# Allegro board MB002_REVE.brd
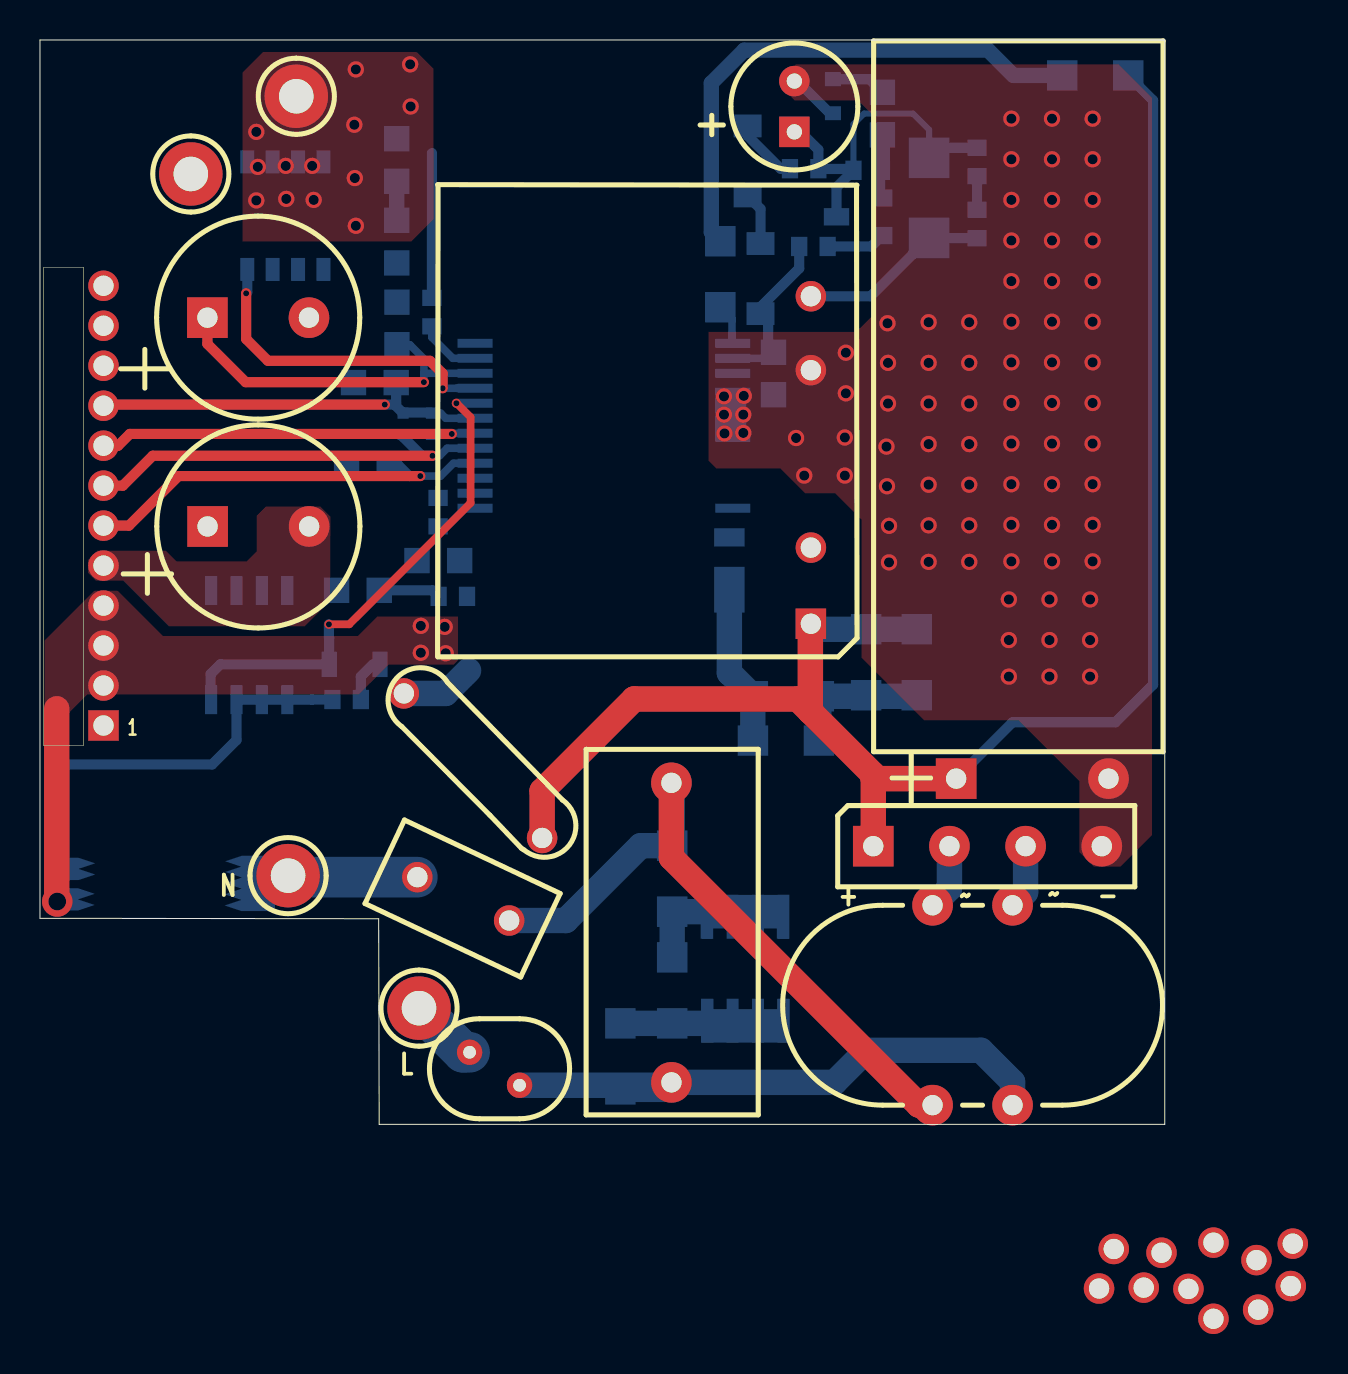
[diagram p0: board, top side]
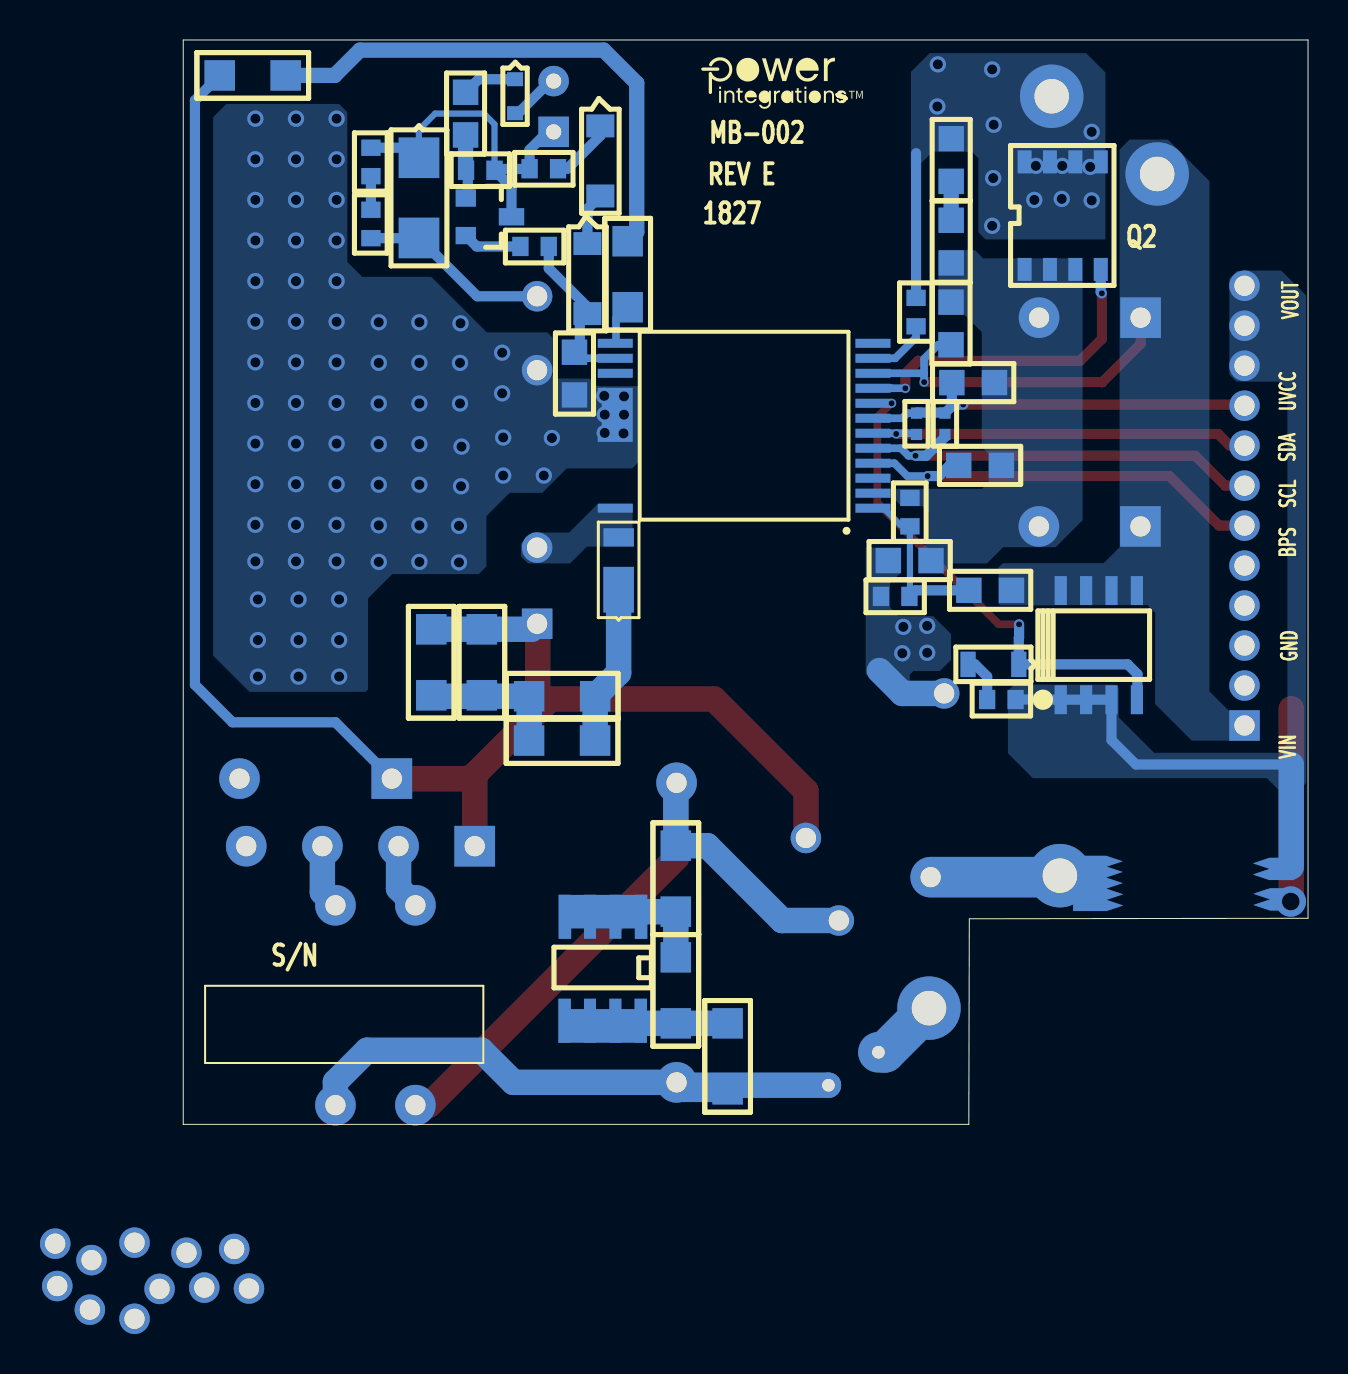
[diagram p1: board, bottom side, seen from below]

Outline 56.26 x 54.25 mm; copper layers: TOP, BOTTOM. Coordinates in mm from the lower left corner of the outline.
Outline path: 0,54.25 0,10.31 16.94,10.29 16.97,0 56.26,0 56.26,54.25 0,54.25

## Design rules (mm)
constraint set DEFAULT: min track width 0.508

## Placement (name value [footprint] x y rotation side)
BR1  KBP306G-BP  [PIDAXBRIDGEKBP306G]  41.68 13.92 0 top
C1  220 nF  [PINPXCAPRAD720X340590040]  31.59 17.09 270 top
C2  82 uF  [PIPOLCAPCLYD600LS300040]  45.83 17.3 0 bottom
C3  470 pF  [PINPCAPRAD374X275LS394D030]  25.12 14.33 133.7 top
C4  2.2 nF  [PISMC1206]  41.33 24.77 270 bottom
C5  56 pF  [PISMC0603]  46.87 45.76 270 bottom
C6  4.7 uF  [PISMC0805]  36.69 38.63 270 bottom
C7  22 uF  [PIPOLCAPCYLD250LS100030]  37.73 49.66 90 top
C8  1 nF  [PISMC0805]  17.85 45.23 270 bottom
C9  2.2 uF  [PISMC0805]  15.34 32.97 0 bottom
C10  2.2 uF  [PISMC0805]  17.86 41.14 270 bottom
C11  2.2 uF  [PISMC0805]  15.68 37.11 0 bottom
C12  470 uF  [PIPOLCAPCYLD400LS200040]  8.38 29.92 0 top
C13  470 uF  [PIPOLCAPCYLD400LS200040]  8.37 40.36 0 top
C14  4.7uF  [PISMC0603]  19.91 31.34 270 bottom
D1  DFLR1800-7  [PISMDDFLR120012]  34.48 26.73 270 bottom
D2  RS1J  [PISMDSMA]  44.47 48.36 270 bottom
D3  BAV21WS-7-F  [PISMSOD323]  14.47 23.02 0 bottom
F1  2 A  [PI_RST_MICROFUSE]  18.88 12.37 334.7 top
FL1  Hole_70mils  [PI_HOLE_70MIL]  7.55 47.57 180 top
FL2  Hole_70mils  [PI_HOLE_70MIL]  12.82 51.46 180 top
J1  PCB Terminal 18 AWG  [PI_HOLE_18AWG]  12.39 12.44 270 top
J2  PCB Terminal 18 AWG  [PI_HOLE_18AWG]  18.96 5.79 0 top
J3  CON15-DNP  [PI_UNSHROUD_2MM_15PRA]  3.18 19.96 90 top
L2  34 mH  [PI_CMCHOKE_19X10MM]  48.65 0.96 180 top
NOREF  -  []  56.21 0 90 top
NOREF#2  -  []  -223.79 -144.77 0 top
NOREF#3  -  []  0 54.25 0 top
NOREF#4  -  []  30.9 53.28 180 bottom
Q1  DSC2C01S0L  [PISMSOT23123_1]  42.13 44.47 270 bottom
Q2  SIR882ADP-T1-GE3  [PI_SM_POWERPAK_SO-8_SINGLE]  14.18 42.77 180 bottom
Q3  AO4354  [PISMSO8]  12.37 21.25 180 bottom
R1  1.91 M  [PISMR1206]  51.13 52.48 0 bottom
R2  1.80 M  [PISMR1206]  34.03 40.88 90 bottom
R3  232 k  [PISMR1206]  43.86 24.77 270 bottom
R4  40.2  [PISMR1206]  38.96 21.42 180 bottom
R5  22  [PISMR0603]  46.87 48.86 270 bottom
R6  22  [PISMR0603]  38.94 47.81 180 bottom
R7  3.74 k  [PISMR0603]  39.4 43.92 180 bottom
R8  243 k  [PISMR0603]  40.69 47.73 0 bottom
R9  10  [PISMR0805]  17.85 47.18 90 bottom
R10  47  [PISMR0603]  19.61 41.35 270 bottom
R11  0.009  [PISMR0805]  20.99 28.21 180 bottom
R13  100  [PISMR0603]  16.05 21.26 180 bottom
R14  4.70 k -DNP  [PISMR0402]  19.58 35.59 270 bottom
R15  4.70 k-DNP  [PISMR0402]  18.16 35.59 270 bottom
R16  2.2 M-DNP  [PISMR1206]  31.62 8.36 270 bottom
R17  2.2 M  [PISMR1206]  31.62 13.94 270 bottom
R18  2.2 M  [PISMR1206]  29.03 5.05 270 bottom
R20  226 k  [PISMR0805]  14.83 26.72 0 bottom
R21  10  [PISMR0603]  19.94 26.42 0 bottom
R22  40.2  [PISMR1206]  38.96 19.2 180 bottom
R23  14.7 k  [PISMR0805]  42.14 49.5 90 bottom
RT1  5  [PI_RAD_276DX197T_LS100D025]  23.99 2.78 180 top
T1  RM8  [PI_BOBBIN_RM8_12P]  38.56 25.05 180 top
U1  INN3368C  [PI_IC_INSOP_24D]  21.76 30.83 0 bottom
U3  CAP200DG  [PI_IC_SMD_SO8_CAPZERO]  33.38 10.39 0 bottom
VR1  DZ2S33000L  [PI_SM_D_SSMINI2P]  39.66 52.29 270 bottom
VR2  MMSZ5262BT1G  [PI_SM_SOD-123_12]  35.4 49.95 270 bottom
VR3  MMSZ5256B-7-F  [PI_SM_SOD-123_12]  36.04 44.07 270 bottom

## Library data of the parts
BR1 = DISCRETE BRIDGE_+~~-
C1 C3-C6 C9-C11 C14 = CAP NP
C2 = CAP POL: alternate symbols: (pipolcapd570ls3000401400lhoriz)
C7 = CAP POL: alternate symbols: (pipolcapcyld250ls100030h)
C8 = CAP NP: alternate symbols: (pismc0805_1)
C12 C13 = CAP POL
D1-D3 = DIODE
F1 = FUSE: alternate symbols: (pirstmicrofusehoz)
FL1 FL2 = FlyingLead
J1 J2 = TERM_1Pin
J3 = CON15
L2 = TORRID 4P_12_34: alternate symbols: (pi_CMChoke_19x10mmH)
Q1 = NPN_BEC
Q2 = FET_N_SGD_123_4_0
Q3 = FET_N_SGD_123_4_5678
R1-R9 R11 R13-R18 R20-R23 = R
R10 = R: alternate symbols: (pismr0603_1)
RT1 = THERMISTOR: alternate symbols: (pi_rad_276DX197Tls100d025H)
T1 = BRM8_12P/GENERIC: alternate symbols: (pi_bobbin_rm8_12p_inline_clp)
U1 = DEV_InnoPro
U3 = CAPZero
VR1-VR3 = DIODE_ZENER

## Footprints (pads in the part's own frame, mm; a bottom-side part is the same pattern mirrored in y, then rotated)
PI_BOBBIN_RM8_12P
  rect 1.524x1.524 hole 1.016: 1(0,0)
  round 1.524 hole 1.016: 2(0,-3.81) 3(-24.105,31.013) 4(0,-12.687) 5(0,-16.386) 6(-24.003,33.134) 7(-15.151,31.28) 8(-17.539,31.468) 9(-22.288,31.836) 10(-22.372,34.315) 11(-20.137,30.963) 12(-20.137,34.773)
PI_CMCHOKE_19X10MM
  round 2.032 hole 1.016: 1(0,0) 2(0,-10) 3(4,0) 4(4,-10)
PI_HOLE_18AWG
  round 3.175 hole 1.727: 1(0,0.025)
PI_HOLE_70MIL
  round 3.175 hole 1.727: 1(0,0.025)
PI_IC_INSOP_24D
  rect 1.75x0.45 smd: 1(0,0) 2(0,-0.75) 3(0,-1.5) 4(0,-2.25) 5(0,-3) 6(0,-3.75) 7(0,-4.5) 8(0,-5.25) 9(0,-6) 10(0,-6.75) 11(0,-7.5) 12(0,-8.25) 13(12.89,-8.25) 14(12.89,-7.5) 15(12.89,-6.75) 24(12.89,0)
  custom 0.438x0.438 smd: 16(12.89,-4.67)
PI_IC_SMD_SO8_CAPZERO
  rect 0.599x2.2 smd: 1(0,0) 2(1.27,0) 3(2.54,0) 4(3.81,0) 5(3.81,5.199) 6(2.54,5.199) 7(1.27,5.199) 8(0,5.199)
PI_RAD_276DX197T_LS100D025
  round 1.27 hole 0.635: 1(0,0.825) 2(2.5,-0.825)
PI_RST_MICROFUSE
  round 1.524 hole 1.016: 1(0,0) 2(5.08,0)
PI_SM_D_SSMINI2P
  rect 0.698x0.8 smd: 1(0,0) 2(1.7,0)
PI_SM_POWERPAK_SO-8_SINGLE
  rect 0.7x1.15 smd: 1(0,0) 2(1.27,0) 3(2.54,0) 4(3.81,0) 5(3.81,5.383) 6(2.54,5.383) 7(1.27,5.383) 8(0,5.383)
PI_SM_SOD-123_12
  rect 1.143x1.397 smd: 1(0,0) 2(3.505,0)
PI_UNSHROUD_2MM_15PRA
  rect 1.524x1.524 hole 1.016: 1(0,0)
  round 1.524 hole 1.016: 2(2,0) 3(4,0) 4(6,0) 5(8,0) 6(10,0) 7(12,0) 8(14,0) 9(16,0) 10(18,0) 11(20,0) 12(22,0) 13(-28.187,-54.268) 14(-28.168,-49.798) 15(-28.124,-52.033)
PIDAXBRIDGEKBP306G
  rect 2.032x2.032 hole 1.016: 1(0,0)
  round 2.032 hole 1.016: 2(3.81,0) 3(7.62,0) 4(11.43,0)
PINPCAPRAD374X275LS394D030
  round 1.524 hole 1.016: 1(0,0) 2(10.008,0)
PINPXCAPRAD720X340590040
  round 2.032 hole 1.016: 1(0,0) 2(14.986,0)
PIPOLCAPCLYD600LS300040
  rect 2.032x2.032 hole 1.016: 1(0,0)
  round 2.032 hole 1.016: 2(7.62,0)
PIPOLCAPCYLD250LS100030
  rect 1.524x1.524 hole 0.762: 1(0,0)
  round 1.524 hole 0.762: 2(2.54,0)
PIPOLCAPCYLD400LS200040
  rect 2.032x2.032 hole 1.016: 1(0,0)
  round 2.032 hole 1.016: 2(5.08,0)
PISMC0603
  rect 0.813x0.965 smd: 1(0,0) 2(1.422,0)
PISMC0805
  rect 1.27x1.27 smd: 1(0,0) 2(2.134,0)
PISMC1206
  rect 1.524x1.524 smd: 1(0,0) 2(3.302,0)
PISMDDFLR120012
  rect 2.286x1.524 smd: 1(-0.025,0)
  rect 0.914x1.524 smd: 2(-2.642,0)
PISMDSMA
  rect 2.032x2.032 smd: 1(0,0) 2(4.013,0)
PISMR0402
  rect 0.559x0.559 smd: 1(0,0) 2(1.067,0)
PISMR0603
  rect 0.813x0.965 smd: 1(0,0) 2(1.422,0)
PISMR0805
  rect 1.27x1.27 smd: 1(0,0) 2(2.134,0)
PISMR1206
  rect 1.524x1.524 smd: 1(0,0) 2(3.302,0)
PISMSO8
  rect 0.61x1.448 smd: 1(0,0) 2(1.27,0) 3(2.54,0) 4(3.81,0) 5(3.81,5.461) 6(2.54,5.461) 7(1.27,5.461) 8(0,5.461)
PISMSOD323
  rect 0.762x1.27 smd: 1(0,0) 2(2.54,0)
PISMSOT23123_1
  rect 0.864x1.016 smd: 1(-1.88,0) 2(0,0)
  rect 0.864x1.27 smd: 3(-0.94,2.286)

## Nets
GND: C3.2 J3.2 J3.3 J3.4 R11.1 R21.2
GND_SIGNAL: C8.2 C9.1 C10.1 C11.1 C12.2 C13.2 C14.1 J3.5 Q2.1(S1) Q2.2 Q2.3 R11.2 U1.2
VBUS_IN: C10.2 C12.1 C13.1 FL1.1 J3.1 Q3.5 Q3.6 Q3.7 Q3.8 R20.1 U1.10(VOUT)
VBUS_OUT: J3.10 J3.11 J3.12 Q3.1 Q3.2 Q3.3(S3) R13.2
BPS: C9.2 J3.6 U1.4
D1: FL2.1 Q2.5 Q2.6 Q2.7 Q2.8 R9.2 R10.1
IS: C14.2 R20.2 R21.1 U1.1
SCL: J3.7 R15.2 U1.5
SDA: J3.8 R14.2 U1.6
UVCC: C11.2 J3.9 R14.1 R15.1 U1.7
N11110124: C1.1 F1.2 L2.3 R17.1
N11110164: C1.2 L2.1 R18.2 RT1.1
N11110441: BR1.2 L2.4
N11110714: BR1.1 C2.1 C3.1 C4.1 R1.2 R3.1 T1.1
N11110720: BR1.4 C2.2 C6.2 C7.2 T1.4 U1.16 VR1.2
N11110824: BR1.3(AC2) L2.2
N11111408: R1.1 R2.2
N11111567: C4.2 R3.2 R4.1 R22.1
N11111589: D1.1 R4.2 R22.2
N11115084: F1.1 J1.1
N11116283: D1.2 T1.2 U1.24
N11116458: R2.1 U1.13
N11116606: Q2.4 U1.9
N11117013: C8.1 R9.1
N11227812: R10.2 U1.11
N12069038: R6.2 VR2.1
N12069042: Q1.1 R8.2 R23.1
N12069064: C7.1 D2.1 Q1.3 R5.1 R6.1 R8.1
N12069074: Q1.2(EMITTER) R7.1
N12069082: C6.1 R7.2 U1.14 VR3.2
N12069477: C5.2 D2.2 T1.5
N12069537: C5.1 R5.2
N12070281: D3.1 Q3.4 U1.8
N12070310: D3.2 R13.1
N12112337: J2.1 RT1.2
N12112817: R16.1 R17.2 U3.2
N12112832: R16.2 R18.1 U3.7
N12122775: VR2.2 VR3.1
N12144048: R23.2 VR1.1

Pads without a net: J3 13 14 15; T1 3 6 7 8 9 10 11 12; U1 3 12 15; U3 1 3 4 5 6 8

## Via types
v1: diameter 1.524, hole 0.889, TOP to BOTTOM, 1 via
v2: diameter 0.457, hole 0.305, TOP to BOTTOM, 9 vias
v3: diameter 0.813, hole 0.508, TOP to BOTTOM, 95 vias

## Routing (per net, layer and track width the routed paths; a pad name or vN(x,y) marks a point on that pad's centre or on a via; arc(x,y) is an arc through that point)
GND: length 13.1
  TOP w1.27: 0.84,20.79 0.84,11.4
  BOTTOM w1.27: C3.2 20.29,21.56 21.44,22.71
  vias: v3(19.05,24.94) v3(19.05,23.6) v3(20.24,24.89) v3(20.29,23.57)
VBUS_IN: length 18.7
  TOP w0.508: C13.1 8.37,39.05 10.29,37.13 v2(19.2,37.13)
  BOTTOM w0.381: 19.21,37.58 19.2,37.58 v2(19.2,37.13) ; 19.21,37.58 19.21,38.3 18.5,39 C10.2 ; 19.21,37.58 U1.10
  BOTTOM w0.508: 2.82,19.94 2.9,19.94 2.92,19.96 J3.1
VBUS_OUT: length 21.4
  BOTTOM w0.508: 0.84,18.01 8.61,18.01 9.83,19.23 Q3.3 Q3.2 Q3.1 13.6,21.25 13.61,21.26 R13.2
  BOTTOM w1.27: 0.84,12.88 0.84,18.01
BPS: length 21.7
  TOP w0.508: J3.6 4.45,29.96 6.93,32.44 v2(19.02,32.44)
  BOTTOM w0.381: v2(19.02,32.44) 20.04,32.44 20.68,33.08 U1.4
  BOTTOM w0.508: v2(19.02,32.44) 18.47,32.44 17.93,32.97 C9.2
D1: length 7.2
  BOTTOM w0.508: 19.61,48.59 R10.1
  vias: v3(10.82,49.66) v3(10.82,46.23) v3(10.9,47.9) v3(12.29,47.96) v3(12.32,46.3) v3(13.61,47.96) v3(13.69,46.25) v3(15.72,50.01) v3(15.75,47.35) v3(15.8,52.78) v3(15.8,44.96) v3(18.52,53.04) v3(18.54,50.93)
IS: length 8.8
  BOTTOM w0.305: 19.91,26.44 C14.2 19.99,30 20.4,30 21.23,30.83 U1.1
  BOTTOM w0.508: R21.1 19.64,26.72 R20.2
Net_8:
  vias: v1(0.86,11.15)
SCL: length 21.4
  TOP w0.508: v2(19.63,33.45) 5.64,33.45 4.14,31.96 J3.7
  BOTTOM w0.381: v2(19.63,33.45) 19.99,33.45 20.37,33.83 U1.5
  BOTTOM w0.508: v2(19.63,33.45) 19.1,33.45 18.16,34.39 R15.2
SDA: length 19.9
  TOP w0.508: v2(20.6,34.54) 4.5,34.54 3.91,33.96 J3.8
  BOTTOM w0.381: 20.56,34.58 19.62,34.58 19.58,34.54 R14.2 ; 20.56,34.58 v2(20.6,34.54) ; 20.56,34.58 U1.6
UVCC: length 20
  TOP w0.508: J3.9 3.23,36.01 v2(17.25,36.01)
  BOTTOM w0.381: 19.61,35.59 20.04,35.59 20.3,35.33 U1.7
  BOTTOM w0.508: 17.73,36.01 R15.1 18.19,35.61 19.56,35.61 R14.1 19.61,35.59 ; 17.73,36.01 v2(17.25,36.01) ; 17.73,36.01 17.82,36.1 C11.2
N11110124: length 34.8
  TOP w1.27: C1.1 31.59,13.35 43.97,0.96 L2.3
  BOTTOM w1.27: F1.2 26.3,10.2 30.05,13.94 R17.1 31.62,17.05 C1.1
N11110164: length 29.7
  BOTTOM w1.27: 31.44,1.96 C1.2 39.75,2.1 41.35,3.71 47.07,3.71 48.65,2.13 L2.1 ; 31.44,1.96 RT1.1 ; 31.44,1.96 31.23,1.75 R18.2
N11110441: length 3.3
  BOTTOM w1.27: BR1.2 45.49,11.81 L2.4
N11110714: length 82.7
  TOP w1.27: 38.53,20.65 41.68,17.5 41.68,17.3 ; 38.53,20.65 38.53,25.02 T1.1 ; 38.53,20.65 37.9,21.29 29.72,21.29 25.12,16.68 C3.1 ; 41.68,17.3 C2.1 ; 41.68,17.3 BR1.1
  BOTTOM w0.508: C2.1 48.65,20.12 53.8,20.12 55.68,22 55.68,51.23 54.44,52.47 R1.2
  BOTTOM w1.27: T1.1 38.84,24.77 C4.1 R3.1
N11110720: length 2.6
  BOTTOM w0.508: VR1.2 39.5,50.59 37.9,52.2 C7.2
  vias: v3(34.21,36.42) v3(34.21,35.51) v3(34.24,34.57) v3(35.2,36.45) v3(35.18,35.51) v3(35.18,34.59) v3(37.82,34.34) v3(38.23,32.46) v3(40.31,38.61) v3(40.31,36.58) v3(40.26,34.37) v3(40.26,32.46) v3(42.34,33.91) v3(42.39,40.08) v3(42.42,38.1) v3(42.42,36.07) v3(42.37,31.93) v3(42.47,29.95) v3(42.47,28.12) v3(44.45,40.13) v3(44.45,38.1) v3(44.45,36.07) v3(44.45,34.04) v3(44.45,32) v3(44.45,29.97) v3(44.45,28.14) v3(46.48,40.13) v3(46.48,38.1) v3(46.48,36.07) v3(46.48,34.04) v3(46.48,32) v3(46.48,29.97) v3(46.48,28.14) v3(48.46,26.26) v3(48.46,24.23) v3(48.46,22.4) v3(48.59,50.32) v3(48.59,48.29) v3(48.59,46.25) v3(48.59,44.22) v3(48.59,42.19) v3(48.59,40.16) v3(48.59,38.13) v3(48.59,36.09) v3(48.59,34.06) v3(48.59,32.03) v3(48.59,30) v3(48.59,28.17) v3(50.5,26.26) v3(50.5,24.23) v3(50.5,22.4) v3(50.62,50.32) v3(50.62,48.29) v3(50.62,46.25) v3(50.62,44.22) v3(50.62,42.19) v3(50.62,40.16) v3(50.62,38.13) v3(50.62,36.09) v3(50.62,34.06) v3(50.62,32.03) v3(50.62,30) v3(50.62,28.17) v3(52.53,26.26) v3(52.53,24.23) v3(52.53,22.4) v3(52.65,50.32) v3(52.65,48.29) v3(52.65,46.25) v3(52.65,44.22) v3(52.65,42.19) v3(52.65,40.16) v3(52.65,38.13) v3(52.65,36.09) v3(52.65,34.06) v3(52.65,32.03) v3(52.65,30) v3(52.65,28.17)
N11110824: length 3.2
  BOTTOM w1.27: BR1.3 49.3,11.62 L2.2
N11111408: length 26.9
  BOTTOM w0.762: R2.2 33.58,44.64 33.58,52.1 35.23,53.75 47.42,53.75 48.69,52.48 R1.1
N11111567: length 7.2
  BOTTOM w1.27: R22.1 38.96,19.21 R4.1 41.28,21.42 C4.2 41.38,21.42 43.8,21.42 R3.2
N11111589: length 8
  BOTTOM w1.27: D1.1 34.48,22.59 R4.2 35.66,19.21 R22.2
N11115084: length 6.5
  BOTTOM w2.032: F1.1 12.49,12.37 J1.1
N11116458: length 2.1
  BOTTOM w0.381: R2.1 34.62,40.3 34.62,39.12 U1.13
N11116606: length 16.4
  TOP w0.508: v2(20.14,36.83) 20.14,37.57 19.51,38.2 11.4,38.2 10.31,39.29 v2(10.31,41.58)
  BOTTOM w0.381: U1.9 20.85,36.83 v2(20.14,36.83)
  BOTTOM w0.508: Q2.4 10.37,41.64 v2(10.31,41.58)
N11117013: length 1.9
  BOTTOM w0.762: R9.1 C8.1
N11227812: length 3.1
  BOTTOM w0.381: U1.11 20.65,38.33 19.61,39.37 R10.2
N12069038: length 3.3
  BOTTOM w0.508: VR2.1 35.4,49.46 37.05,47.81 R6.2
N12069042: length 3.2
  BOTTOM w0.508: R8.2 42.03,47.65 42.03,46.45 Q1.1
  BOTTOM w0.762: R8.2 42.14,47.76 R23.1
N12069064: length 17.6
  BOTTOM w0.305: R8.1 40.69,50.04 41.22,50.57 43.66,50.57 44.48,49.76 44.48,48.37
  BOTTOM w0.508: D2.1 44.97,48.86 R5.1 ; Q1.3 39.84,46.88 R8.1 40.63,47.8 38.95,47.8 R6.1 38.94,48.76 38.04,49.66 C7.1
N12069074: length 3
  BOTTOM w0.508: R7.1 41.58,43.92 Q1.2
N12069082: length 8.5
  BOTTOM w0.381: U1.14 36.26,38.33 36.57,38.63 C6.1
  BOTTOM w0.508: C6.1 36.42,38.9 36.42,40.18 VR3.2 36.04,40.89 37.98,42.83 R7.2
N12069477: length 9.5
  BOTTOM w0.508: 44.47,44.35 44.48,44.34 C5.2 ; 44.47,44.35 41.55,41.43 T1.5 ; 44.47,44.35 D2.2
N12069537: length 1.7
  BOTTOM w0.508: R5.2 C5.1
N12070281: length 25.3
  TOP w0.381: v2(14.45,25.02) 15.47,25.02 21.54,31.09 21.54,35.38 20.84,36.08 v2(20.83,36.08)
  BOTTOM w0.381: U1.8 v2(20.83,36.08)
  BOTTOM w0.508: v2(14.45,25.02) 14.45,24.36 14.47,24.34 D3.1 9.02,23.02 8.53,22.53 8.53,21.27 Q3.4
N12070310: length 2.4
  BOTTOM w0.508: D3.2 16.66,23.02 16.05,22.41 R13.1
N12112337: length 3.4
  BOTTOM w2.032: RT1.2 21.17,3.61 J2.1
N12112817: length 5.4
  BOTTOM w1.27: R16.1 R17.2 34.39,10.64 U3.2
N12112832: length 5.7
  BOTTOM w1.27: U3.7 34.51,5.05 R16.2 R18.1
N12122775: length 2.6
  BOTTOM w0.508: VR3.1 36.04,45.8 VR2.2
N12144048: length 2.7
  BOTTOM w0.508: VR1.1 41.49,52.29 R23.2

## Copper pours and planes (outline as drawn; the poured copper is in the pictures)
GND on TOP: 15.9,24.43 16.88,25.41 20.89,25.41 20.9,25.4 20.9,23.22 20.69,23 17.44,23 15.95,21.51 2.36,21.51 1.37,20.52 0.23,20.52 0.23,24.21 2.72,26.7 3.89,26.7 6.15,24.43
GND on BOTTOM: 22.12,22.53 21.59,22 19.91,22 19.91,22.5 19.74,22.68 18.41,22.68 17.86,23.24 17.86,24.54 18.75,25.43 20.47,25.43 20.91,25.86 20.91,27.07 20.35,27.64 20.35,28.83 20.37,28.85 22.12,28.85
GND_SIGNAL on TOP: 6.3,28.7 6.83,28.17 10.34,28.17 10.85,28.68 10.85,30.45 11.3,30.91 14.02,30.91 14.53,30.4 14.53,29.41 14.52,29.4 14.52,26.2 13.23,24.92 6.45,24.92 4.17,27.2 2.79,27.2 2.4,27.6 2.4,28.23 2.87,28.7
GND_SIGNAL on BOTTOM: 11.28,43.33 16.28,43.33 16.28,43.36 16.66,43.74 18.47,43.74 18.49,43.71 18.49,40.51 17.2,40.51 16.32,39.64 16.32,33.9 15.98,33.55 15.98,32.13 16.31,31.8 22.61,31.8 22.63,31.78 22.63,31.37 20.78,31.37 20.35,30.94 19.28,30.94 19.28,30.91 18.95,30.58 18.95,29.18 19.25,28.88 19.51,28.88 19.51,27.69 19.41,27.58 18.24,27.58 18.03,27.79 18.03,27.86 17.83,28.07 16.05,28.07 15.24,28.88 12.62,28.88 11.28,30.23
VBUS_IN on BOTTOM: 2.39,19.2 5.82,19.2 7.65,21.03 7.65,25.6 8.03,25.98 12.67,25.98 12.69,25.97 15.41,25.97 15.48,26.05 15.48,27.86 15.27,28.08 10.22,28.08 9.42,28.88 9.42,48.77 8.92,49.28 7.01,49.28 4.93,47.19 4.93,21.67 3.96,20.7 2.41,20.7 2.41,19.23
VBUS_OUT on BOTTOM: 2.06,17.32 1.3,16.56 0.61,16.56 0.1,17.07 0.1,41.48 1.35,42.72 3.23,42.72 3.25,42.7 3.56,42.7 3.94,42.32 3.94,37.52 3.58,37.16 1.45,37.16 1.03,36.74 1.03,19.04 1.47,18.59 7.7,18.59 9.47,20.37 9.47,21.84 9.63,22 14.71,22 15.01,21.69 15.01,18.57 13.77,17.32
D1 on TOP: 11.15,53.64 18.85,53.64 19.68,52.81 19.68,45.29 18.57,44.17 10.13,44.17 10.13,52.63
D1 on BOTTOM: 10.13,44.27 16.13,44.27 16.48,44.63 16.48,48.34 16.81,48.67 18.77,48.67 19.53,47.9 19.86,47.9 19.86,52.65 18.92,53.59 11.1,53.59 10.13,52.63
Net_8 on BOTTOM (solid shape): 2.73,11.54 1.89,11.26 2.73,10.98 1.89,10.7 0.68,10.7 0.68,11.82 1.89,11.82
Net_8 on BOTTOM (solid shape): 2.76,13.06 1.92,12.78 2.76,12.5 1.92,12.22 0.7,12.22 0.7,13.34 1.92,13.34
Net_8 on BOTTOM (solid shape): 11.78,11.79 11.75,11.79 11.75,10.67 10.07,10.67 9.24,10.95 10.07,11.23 9.24,11.51 10.07,11.79 10.08,11.8 9.26,12.07 10.1,12.35 9.26,12.63 10.06,12.9 9.26,13.16 10.1,13.44 11.78,13.44
Net_48 on BOTTOM (solid shape): 33.68,5.77 36.88,5.77 36.88,6.27 37.49,6.27 37.49,4.09 33.07,4.09 33.07,6.27 33.68,6.27
Net_52 on BOTTOM (solid shape): 37.47,9.3 36.86,9.3 36.86,9.8 33.66,9.8 33.66,9.3 33.05,9.3 33.05,11.48 37.47,11.48
N11110720 on TOP: 37.29,52.5 37.82,53.04 53.95,53.04 55.62,51.36 55.62,14.48 54.04,12.89 52.72,12.89 51.99,13.61 51.99,17.17 48.95,20.22 44.22,20.22 41.1,23.34 41.1,30.25 39.78,31.57 38.28,31.57 37.03,32.82 33.83,32.82 33.44,33.21 33.44,39.65 38.25,39.65 38.27,39.64 38.28,39.65 40.84,39.65 41.78,40.59 41.78,41.72 41.79,41.73 41.79,50.36 40.92,51.23 37.74,51.23 37.29,51.69
N11110720 on BOTTOM: 48.05,43.15 48.05,50.65 48.46,51.05 54.1,51.05 54.76,50.39 54.76,23.44 52.96,21.64 47.14,21.64 47.02,21.77 47.02,26.31 45.8,27.53 41.48,27.53 41.1,27.91 41.1,30.43 39.93,31.6 38.3,31.6 37.08,32.82 33.81,32.82 33.44,33.18 33.44,36.93 35.56,36.93 35.94,37.31 37.64,37.31 37.8,37.46 37.8,39.37 38.05,39.62 41.07,39.62 43.85,42.41 47.31,42.41
N11116283 on BOTTOM: 35.51,31.06 33.79,31.06 33.79,31.05 33.78,31.04 33.78,28.91 36.07,28.91 36.91,28.07 39.01,28.07 39.37,28.42 39.37,29.06 38.81,29.62 38.81,29.62 36.96,29.62

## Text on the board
Ref Des/Silkscreen Bottom: VOUT | GND | UVCC | SCL | BPS | VIN | SDA | MB-002 | REV E | 1827 | S/N
Ref Des/Silkscreen Top: N | L
User.5: 11.  TRACE SPACE +/- 0.003" | 13. 6 LAYERS BOARD TOP,1, 2, 3, 4, BOTTOM. | 14. VIAS 3, 4, 7, 8, 9, 12, ARE COPPER FILLED.
User.6: SLOT | NOTES: UNLESS OTHERWISE SPECIFIED | 1.  THROUGH HOLES ARE PLATED THROUGH. | 2.  MATERIAL: BASE MATERIAL LAMINATED EPOXY | 3.  SOLDER PLATE WILL BE RoHS COMPLIANT. | 4.  SOLDER MASK LPI (LIQUID PHOTO IMAGEABLE) BOTH SIDES. COLOR GREEN. | 5.  SILKSCREEN TOP/BOTTOM SIDE. COLOR WHITE.(MIN.WIDTH 0.005" MAX.WIDTH 0.010") | 6.  FINISH TO BE SMOBC. | 7.  LEAD FREE HASL (HOT AIR SOLDER LEVEL) OR RoHS COMPLIANT. | 8.  BOARD DIMENTION +/- 0.005" | 9.  DRILL TOLERANCE+/-0.003" | 10.  TRACE WIDTH UNDER 0.010" +/- 0.002" | 11.  TRACE SPACE +/- 0.003" | 12.  MATERIAL FR4 COPPER 2 OZ TOTAL BOARD THICKNESS 0.062" | PLEASE DELETE THESE PINS | EXCEPTIONS WILL BE NOTED IN DRILL CHART "NOTE". | UL APPROVED MANUFACTURED SOURCE FOR FR4. | SOLDER MASK (REGISTRATION) -0/+0.003" | TRACE WIDTH OVER 0.011" +/- 0.005"
User.9: FIGURE | FINISHED_SIZE | 12.012 | 20.0 | 25.0 | 30.0 | 35.0 | 40.0 | 67.988 | DRILL CHART: TOP to BOTTOM | ALL UNITS ARE IN MILS | TOLERANCE_DRILL | +2.988/-2.988 | +0.0/-0.0 | PLATED | QTY | 9 | 95 | 2 | 1 | 12 | 24 | 11 | 4
